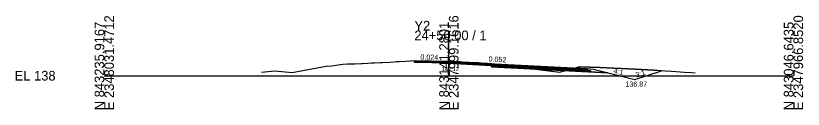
# Model space of a CAD drawing. Extents: x -26 to 2346977, y -10 to 843253.
# Drawn here: x 1174.3 to 1402.8, y -9.7 to 17.3 of the extents above; entities that cross this region are included whole.
import ezdxf

# ---------------------------------------------------------------- set-up
doc = ezdxf.new("R2010")
doc.units = 0
for name, color, linetype in [('Exist Cross Section Cell', 7, 'Continuous'), ('Exist XS Center Line Elevation Label', 7, 'Continuous'), ('Exist XS Ground Line', 7, 'Continuous'), ('Prop CMT Pvmt Course 1', 7, 'Continuous'), ('Prop CMT Pvmt Course 2', 7, 'Continuous'), ('Prop CMT Pvmt Course 2 Wedge', 7, 'Continuous'), ('Prop CMT Pvmt Course 3', 7, 'Continuous'), ('Prop CMT Pvmt Course 3 Wedge', 7, 'Continuous'), ('Prop CMT Pvmt Surface', 7, 'Continuous'), ('Prop CMT Pvmt Surface Shoulder', 7, 'Continuous'), ('Prop CMT Pvmt Wedge Surface 1', 7, 'Continuous'), ('Prop CMT Pvmt Wedge Surface 2', 7, 'Continuous'), ('Prop CMT Pvmt Wedge Surface 3', 7, 'Continuous'), ('Prop CMT Shld Paved Course 1', 7, 'Continuous'), ('Prop CMT Shld Paved Course 2', 7, 'Continuous'), ('Prop CMT Shld Paved Course 3', 7, 'Continuous'), ('Prop CMT Slope Grass', 7, 'Continuous'), ('Prop CMT Subgrade Earthwork', 7, 'Continuous'), ('Prop Road Sect_ Recs - UUC (pattern)', 7, 'Continuous'), ('Prop XS Earthwork Shape', 7, 'Continuous'), ('Prop XS SE Text', 7, 'Continuous')]:
    doc.layers.add(name, color=color, linetype=linetype)

msp = doc.modelspace()

# ---------------------------------------------------------------- linework, layer by layer
at = {"layer": 'Exist Cross Section Cell'}
for p, q in [((1300, 0), (1300, 13.07)), ((1200, 0), (1300, 0)), ((1300, 0), (1400, 0))]:
    msp.add_line(p, q, dxfattribs=at)
at = {"layer": 'Exist XS Ground Line'}
msp.add_lwpolyline([(1245.66, 1.05), (1249.47, 1.41), (1254.52, 0.97), (1264.9, 2.84), (1265.32, 2.75), (1267.92, 3.12), (1269.21, 3.35), (1270.57, 3.4), (1271.18, 3.41), (1272.68, 3.44), (1274.51, 3.56), (1274.98, 3.58), (1276.45, 3.67), (1277.61, 3.73), (1278.43, 3.76), (1280.27, 3.86), (1280.77, 3.87), (1282.86, 3.94), (1284.01, 4.01), (1284.8, 4.1), (1285.63, 4.12), (1287.45, 4.25), (1288.88, 4.33), (1289.3, 4.36), (1290.08, 4.35), (1291.64, 4.32), (1292.71, 4.3), (1293.62, 4.28), (1295.57, 4.24), (1296.22, 4.22), (1297.56, 4.19), (1298.01, 4.17), (1300, 4.12), (1300.57, 4.1), (1301.09, 4.07), (1303.26, 3.97), (1303.89, 3.94), (1305.9, 3.85), (1307.37, 3.76), (1308.55, 3.69), (1309.33, 3.65), (1311.19, 3.54), (1312.34, 3.48), (1312.75, 3.42), (1332.12, 1.07), (1335.65, 1.95), (1337.85, 2.54), (1343.84, 2.34), (1354.06, 1.9), (1359.44, 1.59), (1364.63, 1.28), (1368.39, 1.04), (1370.43, 0.97), (1371.52, 0.85)], dxfattribs=at)
at = {"layer": 'Prop CMT Pvmt Course 1'}
for p, q in [((1300, 4.12), (1290, 4.35)), ((1300, 4.12), (1331.99, 2.45)), ((1300, 3.87), (1300, 4.12)), ((1300, 3.87), (1300, 4.12)), ((1300, 3.99), (1312.34, 3.36)), ((1300, 3.99), (1300, 3.87)), ((1300, 3.99), (1300, 3.87)), ((1300, 3.87), (1300, 3.87)), ((1300, 3.87), (1300, 3.87)), ((1312.34, 3.23), (1331.98, 2.2)), ((1340, 1.79), (1312.34, 3.23)), ((1340, 2.04), (1340, 1.79))]:
    msp.add_line(p, q, dxfattribs=at)
at = {"layer": 'Prop CMT Pvmt Course 2'}
for p, q in [((1331.99, 1.95), (1314.86, 2.85)), ((1340, 1.79), (1340, 1.54))]:
    msp.add_line(p, q, dxfattribs=at)
at = {"layer": 'Prop CMT Pvmt Course 2 Wedge'}
for q in [(1290, 4.1), (1312.21, 3.23)]:
    msp.add_line((1300, 3.87), q, dxfattribs=at)
at = {"layer": 'Prop CMT Pvmt Course 3'}
for p, q in [((1312.34, 2.98), (1340, 1.54)), ((1331.99, 1.58), (1314.82, 2.48)), ((1340, 1.54), (1340, 1.16))]:
    msp.add_line(p, q, dxfattribs=at)
at = {"layer": 'Prop CMT Pvmt Course 3 Wedge'}
for p, q in [((1300.01, 3.62), (1290, 3.85)), ((1300, 3.62), (1312.21, 2.98))]:
    msp.add_line(p, q, dxfattribs=at)
at = {"layer": 'Prop CMT Pvmt Surface'}
for q in [(1290, 4.35), (1340, 2.04)]:
    msp.add_line((1300, 4.12), q, dxfattribs=at)
at = {"layer": 'Prop CMT Pvmt Surface Shoulder'}
msp.add_line((1340, 2.04), (1340, 2.04), dxfattribs=at)
at = {"layer": 'Prop CMT Pvmt Wedge Surface 1'}
for p, q in [((1314.88, 3.1), (1331.99, 2.2)), ((1340, 1.79), (1340, 2.04))]:
    msp.add_line(p, q, dxfattribs=at)
at = {"layer": 'Prop CMT Pvmt Wedge Surface 2'}
for p, q in [((1290, 3.85), (1290, 4.35)), ((1300, 3.99), (1290, 4.23)), ((1300, 3.87), (1290, 4.1)), ((1300, 3.87), (1340, 1.79)), ((1340, 1.79), (1340, 2.04))]:
    msp.add_line(p, q, dxfattribs=at)
at = {"layer": 'Prop CMT Pvmt Wedge Surface 3'}
for p, q in [((1300.01, 3.62), (1290, 3.85)), ((1300, 3.62), (1340, 1.54)), ((1340, 1.54), (1340, 2.04))]:
    msp.add_line(p, q, dxfattribs=at)
at = {"layer": 'Prop CMT Shld Paved Course 1'}
for p, q in [((1340, 2.04), (1340, 2.04)), ((1340, 2.04), (1340.25, 1.78)), ((1340, 1.79), (1340, 2.04)), ((1340.25, 1.78), (1340, 1.79))]:
    msp.add_line(p, q, dxfattribs=at)
at = {"layer": 'Prop CMT Shld Paved Course 2'}
for p, q in [((1340, 1.79), (1340.25, 1.78)), ((1340, 1.54), (1340, 1.79)), ((1340.51, 1.53), (1340, 1.54)), ((1340.25, 1.78), (1340.51, 1.53))]:
    msp.add_line(p, q, dxfattribs=at)
at = {"layer": 'Prop CMT Shld Paved Course 3'}
for p, q in [((1340, 1.54), (1340.51, 1.53)), ((1340, 1.16), (1340, 1.54)), ((1341.43, 1.09), (1340, 1.16)), ((1340.51, 1.53), (1341.01, 1.51)), ((1341.01, 1.51), (1341.43, 1.09))]:
    msp.add_line(p, q, dxfattribs=at)
at = {"layer": 'Prop CMT Slope Grass'}
for p, q in [((1340, 2.04), (1342, 1.87)), ((1342, 1.87), (1354, -1.13)), ((1354, -1.13), (1361.75, 1.45))]:
    msp.add_line(p, q, dxfattribs=at)
at = {"layer": 'Prop CMT Subgrade Earthwork'}
for p, q in [((1312.34, 2.6), (1312.34, 3.48)), ((1312.34, 2.61), (1346.11, 0.84))]:
    msp.add_line(p, q, dxfattribs=at)
at = {"layer": 'Prop Road Sect_ Recs - UUC (pattern)'}
msp.add_line((1334.04, 1.47), (1334.15, 1.58), dxfattribs=at)
msp.add_line((1334.04, 1.47), (1334.15, 1.58), dxfattribs=at)
msp.add_line((1334.04, 1.47), (1334.15, 1.58), dxfattribs=at)
at = {"layer": 'Prop XS Earthwork Shape'}
for points in [[(1290.08, 4.35), (1291.64, 4.32), (1292.71, 4.3), (1293.62, 4.28), (1295.57, 4.24), (1296.22, 4.22), (1297.56, 4.19), (1298.01, 4.17), (1300, 4.12), (1290, 4.35)], [(1300, 4.12), (1312.34, 3.48), (1311.19, 3.54), (1309.33, 3.65), (1308.55, 3.69), (1307.37, 3.76), (1305.9, 3.85), (1303.89, 3.94), (1303.26, 3.97), (1301.09, 4.07), (1300.57, 4.1)], [(1312.34, 3.48), (1312.75, 3.42), (1324.9, 1.95), (1312.34, 2.61)], [(1346.11, 0.84), (1354, -1.13), (1361.75, 1.45), (1359.44, 1.59), (1354.06, 1.9), (1343.84, 2.34), (1337.85, 2.54), (1336.63, 2.21), (1340, 2.04), (1342, 1.87)], [(1324.9, 1.95), (1332.12, 1.07), (1333.77, 1.49)], [(1340, 2.04), (1342, 1.87), (1346.11, 0.84), (1333.77, 1.49), (1335.65, 1.95), (1336.63, 2.21)]]:
    msp.add_lwpolyline(points, close=True, dxfattribs=at)

# ---------------------------------------------------------------- texts
at = {"layer": 'Exist Cross Section Cell'}
for s, p in [('E 2348031.4712', (1202.8, -10)), ('E 2347999.1616', (1302.8, -10)), ('E 2347966.8520', (1402.8, -10)), ('N 843235.9167', (1200, -10)), ('N 843141.2801', (1300, -10)), ('N 843046.6435', (1400, -10))]:
    msp.add_text(s, height=2.8, rotation=90, dxfattribs=at).set_placement(p)
for s, p in [('Y2', (1290, 13.07)), ('24+50.00 / 1', (1290, 10.27)), ('EL 138', (1174, -1.4))]:
    msp.add_text(s, height=2.8, dxfattribs=at).set_placement(p)
at = {"layer": 'Exist XS Center Line Elevation Label'}
msp.add_text('142.12', height=1.2, dxfattribs=at).set_placement((1297.89, 1.32))
at = {"layer": 'Prop XS SE Text'}
for s, rotation, p in [('0.024', 358.6466, (1291.73, 4.69)), ('0.052', 357.0239, (1311.48, 4.14)), ('4:1', 345.9638, (1347.67, 0.79)), ('3:1', 18.4349, (1354.44, -0.56)), ('136.87', 360, (1351.21, -3.18))]:
    msp.add_text(s, height=1.5, rotation=rotation, dxfattribs=at).set_placement(p)

doc.saveas('drawing.dxf')
